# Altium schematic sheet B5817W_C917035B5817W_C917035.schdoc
size 127 x 101 mm
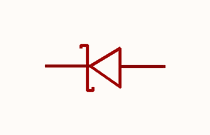
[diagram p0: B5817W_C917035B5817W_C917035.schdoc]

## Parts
D?  b5817w_c917035  [SOD-123_L2.7-W1.6-LS3.7-RD]  (value not drawn)

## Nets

Not connected (* = marked no-connect by the designer): D? 1(K) 2(A)

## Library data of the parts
D? = b5817w_c917035: 二极管配置:独立式;正向压降(Vf):450mV@1A;直流反向耐压(Vr):20V;整流电流:1A;; Manufacturer: JSMSEMI(杰盛微); ManufacturerPart: B5817W; AddInBom: yes; ModelId: ad7e39f9e5534b3c96ffdc5532ebb493; ModelName: SOD-123_L2.7-W1.6-H1.4-LS3.7; ModelTransform: 146.026,62.992,0,180,0,0,0.0005,0,0; Diode Configuration: 独立式; Voltage - DC Reverse(Vr): 20V; Current - Rectified: 1A; Reverse Leakage Current (Ir): 1mA@20V; Operating Junction Temperature Range: -65℃~+100℃; Non-Repetitive Peak Forward Surge Current: 10A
